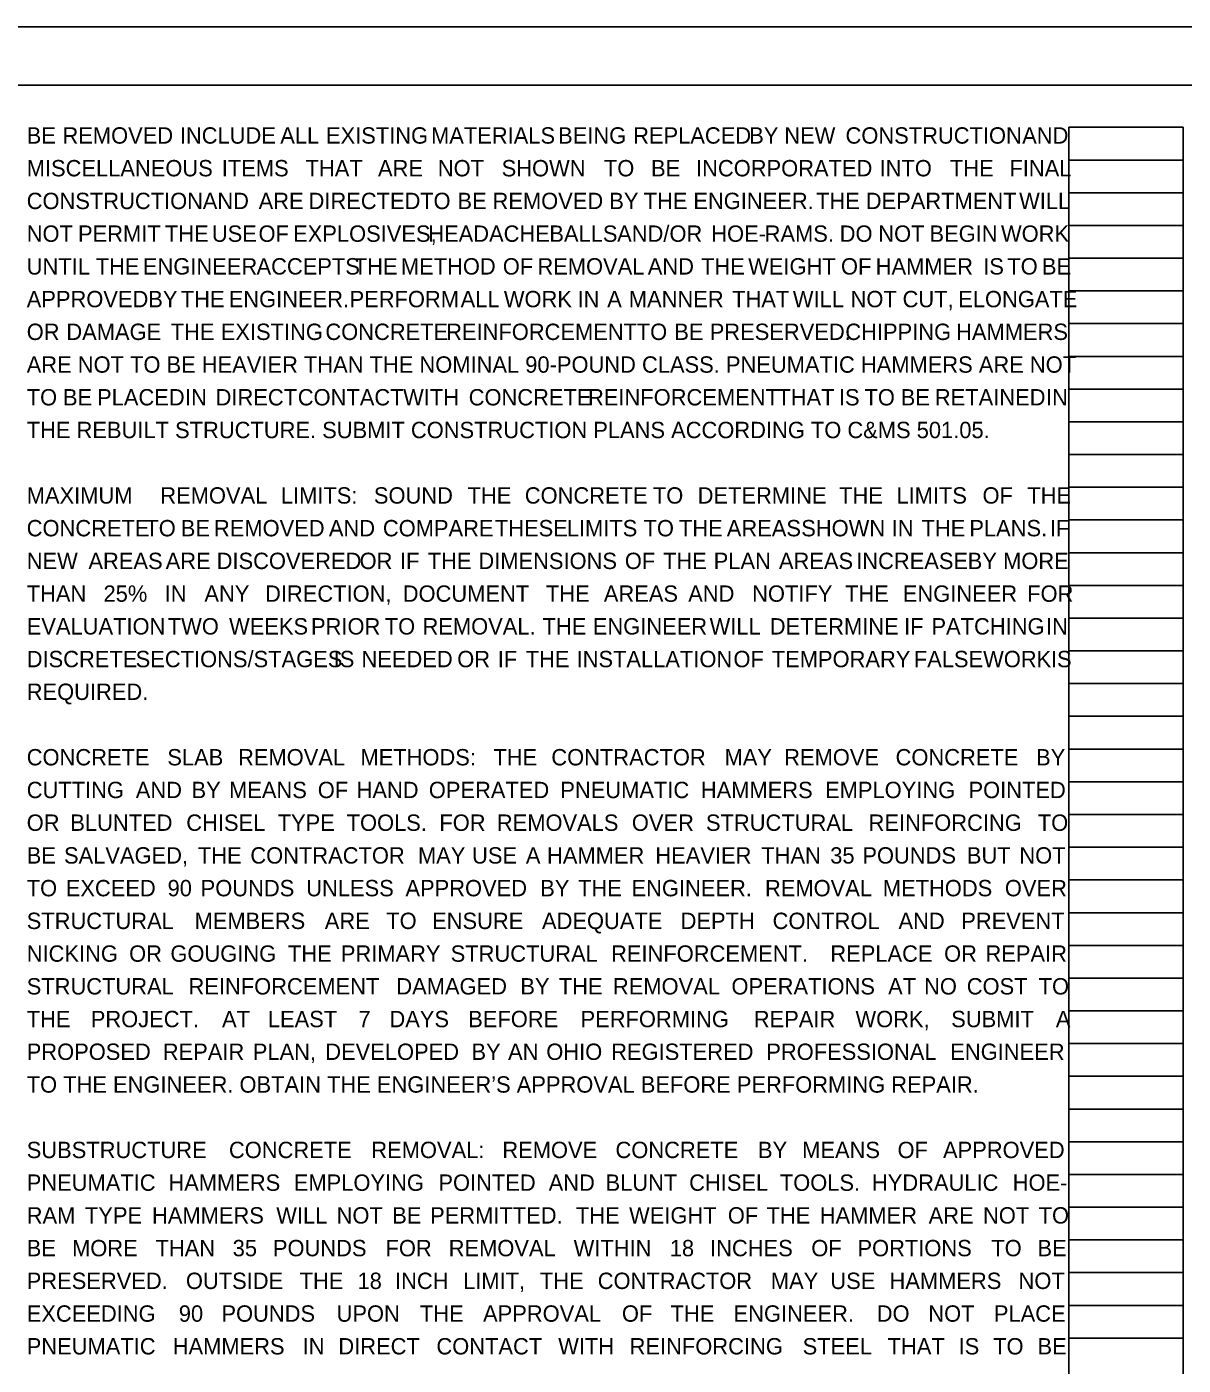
# Model space of a CAD drawing. Extents: x 0 to 44.4, y -4.7 to 22.
# Drawn here: x 12.29 to 22.19, y 10.55 to 22 of the extents above; entities that cross this region are included whole.
import ezdxf

# ---------------------------------------------------------------- set-up
doc = ezdxf.new("R2010")
doc.units = 0
for name, color, linetype in [('SC_Scratch1', 7, 'Continuous'), ('SH_Border', 7, 'Continuous'), ('SH_Cut_Line', 7, 'Continuous'), ('SH_Text', 7, 'Continuous')]:
    doc.layers.add(name, color=color, linetype=linetype)

msp = doc.modelspace()

# ---------------------------------------------------------------- linework, layer by layer
at = {"layer": 'SC_Scratch1'}
for p, q in [((21.207, 0.98), (21.207, 21.14)), ((21.207, 21.14), (22.187, 21.14)), ((22.187, 0.98), (22.187, 21.14)), ((21.207, 20.86), (22.187, 20.86)), ((21.207, 20.58), (22.187, 20.58)), ((21.207, 20.3), (22.187, 20.3)), ((21.207, 20.02), (22.187, 20.02)), ((21.207, 19.74), (22.187, 19.74)), ((21.207, 19.46), (22.187, 19.46)), ((21.207, 19.18), (22.187, 19.18)), ((21.207, 18.9), (22.187, 18.9)), ((21.207, 18.62), (22.187, 18.62)), ((21.207, 18.34), (22.187, 18.34)), ((21.207, 18.06), (22.187, 18.06)), ((21.207, 17.78), (22.187, 17.78)), ((21.207, 17.5), (22.187, 17.5)), ((21.207, 17.22), (22.187, 17.22)), ((21.207, 16.94), (22.187, 16.94)), ((21.207, 16.66), (22.187, 16.66)), ((21.207, 16.38), (22.187, 16.38)), ((21.207, 16.1), (22.187, 16.1)), ((21.207, 15.82), (22.187, 15.82)), ((21.207, 15.54), (22.187, 15.54)), ((21.207, 15.26), (22.187, 15.26)), ((21.207, 14.98), (22.187, 14.98)), ((21.207, 14.7), (22.187, 14.7)), ((21.207, 14.42), (22.187, 14.42)), ((21.207, 14.14), (22.187, 14.14)), ((21.207, 13.86), (22.187, 13.86)), ((21.207, 13.58), (22.187, 13.58)), ((21.207, 13.3), (22.187, 13.3)), ((21.207, 13.02), (22.187, 13.02)), ((21.207, 12.74), (22.187, 12.74)), ((21.207, 12.46), (22.187, 12.46)), ((21.207, 12.18), (22.187, 12.18)), ((21.207, 11.9), (22.187, 11.9)), ((21.207, 11.62), (22.187, 11.62)), ((21.207, 11.34), (22.187, 11.34)), ((21.207, 11.06), (22.187, 11.06)), ((21.207, 10.78), (22.187, 10.78))]:
    msp.add_line(p, q, dxfattribs=at)
msp.add_lwpolyline([(0, 22), (34, 22), (34, 0), (0, 0)], close=True, dxfattribs=at)
at = {"layer": 'SH_Border'}
msp.add_lwpolyline([(1.5, 21.5), (33.5, 21.5), (33.5, 0.5), (1.5, 0.5)], close=True, dxfattribs=at)
at = {"layer": 'SH_Cut_Line'}
msp.add_lwpolyline([(0, 0), (34, 0), (34, 22), (0, 22)], close=True, dxfattribs=at)

# ---------------------------------------------------------------- texts
at = {"layer": 'SH_Text'}
for s, p in [('BE ', (12.293, 21)), ('REMOVED ', (12.599, 21)), ('INCLUDE ', (13.603, 21)), ('ALL ', (14.462, 21)), ('EXISTING ', (14.853, 21)), ('MATERIALS ', (15.752, 21)), ('BEING ', (16.839, 21)), ('REPLACED ', (17.481, 21)), ('BY ', (18.474, 21)), ('NEW ', (18.774, 21)), ('CONSTRUCTION ', (19.298, 21)), ('AND ', (20.809, 21)), ('MISCELLANEOUS ', (12.293, 20.72)), ('ITEMS ', (13.962, 20.72)), ('THAT ', (14.679, 20.72)), ('ARE ', (15.298, 20.72)), ('NOT ', (15.81, 20.72)), ('SHOWN ', (16.356, 20.72)), ('TO ', (17.231, 20.72)), ('BE ', (17.634, 20.72)), ('INCORPORATED ', (18.019, 20.72)), ('INTO ', (19.589, 20.72)), ('THE ', (20.191, 20.72)), ('FINAL ', (20.7, 20.72)), ('CONSTRUCTION ', (12.293, 20.44)), ('AND ', (13.799, 20.44)), ('ARE ', (14.277, 20.44)), ('DIRECTED ', (14.704, 20.44)), ('TO ', (15.659, 20.44)), ('BE ', (15.978, 20.44)), ('REMOVED ', (16.278, 20.44)), ('BY ', (17.277, 20.44)), ('THE ', (17.571, 20.44)), ('ENGINEER. ', (17.996, 20.44)), ('THE ', (19.046, 20.44)), ('DEPARTMENT ', (19.471, 20.44)), ('WILL ', (20.783, 20.44)), ('NOT ', (12.293, 20.16)), ('PERMIT ', (12.732, 20.16)), ('THE ', (13.475, 20.16)), ('USE ', (13.877, 20.16)), ('OF ', (14.276, 20.16)), ('EXPLOSIVES, ', (14.572, 20.16)), ('HEADACHE ', (15.728, 20.16)), ('BALLS ', (16.764, 20.16)), ('AND/OR ', (17.344, 20.16)), ('HOE-', (18.149, 20.16)), ('RAMS. ', (18.606, 20.16)), ('DO ', (19.248, 20.16)), ('NOT ', (19.578, 20.16)), ('BEGIN ', (20.016, 20.16)), ('WORK ', (20.628, 20.16)), ('UNTIL ', (12.293, 19.88)), ('THE ', (12.883, 19.88)), ('ENGINEER ', (13.287, 19.88)), ('ACCEPTS ', (14.259, 19.88)), ('THE ', (15.091, 19.88)), ('METHOD ', (15.494, 19.88)), ('OF ', (16.366, 19.88)), ('REMOVAL ', (16.662, 19.88)), ('AND ', (17.606, 19.88)), ('THE ', (18.062, 19.88)), ('WEIGHT ', (18.465, 19.88)), ('OF ', (19.259, 19.88)), ('HAMMER ', (19.556, 19.88)), ('IS ', (20.476, 19.88)), ('TO ', (20.682, 19.88)), ('BE ', (20.978, 19.88)), ('APPROVED ', (12.293, 19.6)), ('BY ', (13.333, 19.6)), ('THE ', (13.611, 19.6)), ('ENGINEER. ', (14.021, 19.6)), ('PERFORM ', (15.055, 19.6)), ('ALL ', (16.005, 19.6)), ('WORK ', (16.375, 19.6)), ('IN ', (17.005, 19.6)), ('A ', (17.259, 19.6)), ('MANNER ', (17.444, 19.6)), ('THAT ', (18.328, 19.6)), ('WILL ', (18.847, 19.6)), ('NOT ', (19.341, 19.6)), ('CUT, ', (19.786, 19.6)), ('ELONGATE ', (20.262, 19.6)), ('OR ', (12.293, 19.32)), ('DAMAGE ', (12.632, 19.32)), ('THE ', (13.525, 19.32)), ('EXISTING ', (13.953, 19.32)), ('CONCRETE ', (14.848, 19.32)), ('REINFORCEMENT ', (15.881, 19.32)), ('TO ', (17.512, 19.32)), ('BE ', (17.833, 19.32)), ('PRESERVED. ', (18.136, 19.32)), ('CHIPPING ', (19.296, 19.32)), ('HAMMERS ', (20.244, 19.32)), ('ARE NOT TO BE HEAVIER THAN THE NOMINAL 90-POUND CLASS. PNEUMATIC HAMMERS ARE NOT ', (12.293, 19.04)), ('TO ', (12.293, 18.76)), ('BE ', (12.603, 18.76)), ('PLACED ', (12.895, 18.76)), ('IN ', (13.647, 18.76)), ('DIRECT ', (13.909, 18.76)), ('CONTACT ', (14.612, 18.76)), ('WITH ', (15.513, 18.76)), ('CONCRETE ', (16.074, 18.76)), ('REINFORCEMENT ', (17.095, 18.76)), ('THAT ', (18.715, 18.76)), ('IS ', (19.241, 18.76)), ('TO ', (19.46, 18.76)), ('BE ', (19.77, 18.76)), ('RETAINED ', (20.062, 18.76)), ('IN ', (21.013, 18.76)), ('THE REBUILT STRUCTURE. SUBMIT CONSTRUCTION PLANS ACCORDING TO C&MS 501.05. ', (12.293, 18.48)), ('MAXIMUM ', (12.293, 17.92)), ('REMOVAL ', (13.436, 17.92)), ('LIMITS: ', (14.467, 17.92)), ('SOUND ', (15.263, 17.92)), ('THE ', (16.064, 17.92)), ('CONCRETE ', (16.554, 17.92)), ('TO ', (17.65, 17.92)), ('DETERMINE ', (18.033, 17.92)), ('THE ', (19.243, 17.92)), ('LIMITS ', (19.733, 17.92)), ('OF ', (20.47, 17.92)), ('THE ', (20.853, 17.92)), ('CONCRETE ', (12.293, 17.64)), ('TO ', (13.308, 17.64)), ('BE ', (13.611, 17.64)), ('REMOVED ', (13.895, 17.64)), ('AND ', (14.878, 17.64)), ('COMPARE ', (15.34, 17.64)), ('THESE ', (16.298, 17.64)), ('LIMITS ', (16.913, 17.64)), ('TO ', (17.57, 17.64)), ('THE ', (17.873, 17.64)), ('AREAS ', (18.282, 17.64)), ('SHOWN ', (18.919, 17.64)), ('IN ', (19.693, 17.64)), ('THE ', (19.948, 17.64)), ('PLANS. ', (20.357, 17.64)), ('IF ', (21.046, 17.64)), ('NEW ', (12.293, 17.36)), ('AREAS ', (12.821, 17.36)), ('ARE ', (13.482, 17.36)), ('DISCOVERED ', (13.918, 17.36)), ('OR ', (15.141, 17.36)), ('IF ', (15.486, 17.36)), ('THE ', (15.724, 17.36)), ('DIMENSIONS ', (16.157, 17.36)), ('OF ', (17.41, 17.36)), ('THE ', (17.737, 17.36)), ('PLAN ', (18.17, 17.36)), ('AREAS ', (18.728, 17.36)), ('INCREASE ', (19.389, 17.36)), ('BY ', (20.343, 17.36)), ('MORE ', (20.646, 17.36)), ('THAN ', (12.293, 17.08)), ('25% ', (12.95, 17.08)), ('IN ', (13.473, 17.08)), ('ANY ', (13.813, 17.08)), ('DIRECTION, ', (14.332, 17.08)), ('DOCUMENT ', (15.51, 17.08)), ('THE ', (16.735, 17.08)), ('AREAS ', (17.23, 17.08)), ('AND ', (17.952, 17.08)), ('NOTIFY ', (18.499, 17.08)), ('THE ', (19.294, 17.08)), ('ENGINEER ', (19.788, 17.08)), ('FOR ', (20.852, 17.08)), ('EVALUATION ', (12.293, 16.8)), ('TWO ', (13.5, 16.8)), ('WEEKS ', (14.024, 16.8)), ('PRIOR ', (14.725, 16.8)), ('TO ', (15.356, 16.8)), ('REMOVAL. ', (15.679, 16.8)), ('THE ', (16.706, 16.8)), ('ENGINEER ', (17.136, 16.8)), ('WILL ', (18.135, 16.8)), ('DETERMINE ', (18.65, 16.8)), ('IF ', (19.799, 16.8)), ('PATCHING ', (20.033, 16.8)), ('IN ', (21.013, 16.8)), ('DISCRETE ', (12.293, 16.52)), ('SECTIONS/STAGES ', (13.225, 16.52)), ('IS ', (14.919, 16.52)), ('NEEDED ', (15.157, 16.52)), ('OR ', (15.976, 16.52)), ('IF ', (16.323, 16.52)), ('THE ', (16.562, 16.52)), ('INSTALLATION ', (16.997, 16.52)), ('OF ', (18.339, 16.52)), ('TEMPORARY ', (18.667, 16.52)), ('FALSEWORK ', (19.882, 16.52)), ('IS ', (21.055, 16.52)), ('REQUIRED.', (12.293, 16.24)), ('CONCRETE ', (12.293, 15.68)), ('SLAB ', (13.496, 15.68)), ('REMOVAL ', (14.101, 15.68)), ('METHODS: ', (15.148, 15.68)), ('THE ', (16.285, 15.68)), ('CONTRACTOR ', (16.781, 15.68)), ('MAY ', (18.263, 15.68)), ('REMOVE ', (18.773, 15.68)), ('CONCRETE ', (19.726, 15.68)), ('BY ', (20.928, 15.68)), ('CUTTING ', (12.293, 15.4)), ('AND ', (13.226, 15.4)), ('BY ', (13.703, 15.4)), ('MEANS ', (14.024, 15.4)), ('OF ', (14.783, 15.4)), ('HAND ', (15.115, 15.4)), ('OPERATED ', (15.733, 15.4)), ('PNEUMATIC ', (16.858, 15.4)), ('HAMMERS ', (18.06, 15.4)), ('EMPLOYING ', (19.123, 15.4)), ('POINTED ', (20.35, 15.4)), ('OR ', (12.293, 15.12)), ('BLUNTED ', (12.666, 15.12)), ('CHISEL ', (13.658, 15.12)), ('TYPE ', (14.44, 15.12)), ('TOOLS. ', (15.03, 15.12)), ('FOR ', (15.823, 15.12)), ('REMOVALS ', (16.315, 15.12)), ('OVER ', (17.47, 15.12)), ('STRUCTURAL ', (18.104, 15.12)), ('REINFORCING ', (19.495, 15.12)), ('TO ', (20.943, 15.12)), ('BE ', (12.293, 14.84)), ('SALVAGED, ', (12.612, 14.84)), ('THE ', (13.757, 14.84)), ('CONTRACTOR ', (14.206, 14.84)), ('MAY ', (15.64, 14.84)), ('USE ', (16.103, 14.84)), ('A ', (16.563, 14.84)), ('HAMMER ', (16.744, 14.84)), ('HEAVIER ', (17.671, 14.84)), ('THAN ', (18.577, 14.84)), ('35 ', (19.167, 14.84)), ('POUNDS ', (19.442, 14.84)), ('BUT ', (20.336, 14.84)), ('NOT ', (20.785, 14.84)), ('TO ', (12.293, 14.56)), ('EXCEED ', (12.627, 14.56)), ('90 ', (13.498, 14.56)), ('POUNDS ', (13.781, 14.56)), ('UNLESS ', (14.684, 14.56)), ('APPROVED ', (15.533, 14.56)), ('BY ', (16.686, 14.56)), ('THE ', (17.01, 14.56)), ('ENGINEER. ', (17.467, 14.56)), ('REMOVAL ', (18.609, 14.56)), ('METHODS ', (19.617, 14.56)), ('OVER ', (20.661, 14.56)), ('STRUCTURAL ', (12.293, 14.28)), ('MEMBERS ', (13.729, 14.28)), ('ARE ', (14.843, 14.28)), ('TO ', (15.369, 14.28)), ('ENSURE ', (15.761, 14.28)), ('ADEQUATE ', (16.701, 14.28)), ('DEPTH ', (17.887, 14.28)), ('CONTROL ', (18.674, 14.28)), ('AND ', (19.751, 14.28)), ('PREVENT ', (20.288, 14.28)), ('NICKING ', (12.293, 14)), ('OR ', (13.169, 14)), ('GOUGING ', (13.522, 14)), ('THE ', (14.528, 14)), ('PRIMARY ', (14.98, 14)), ('STRUCTURAL ', (15.92, 14)), ('REINFORCEMENT.  ', (17.292, 14)), ('REPLACE ', (19.168, 14)), ('OR ', (20.141, 14)), ('REPAIR ', (20.495, 14)), ('STRUCTURAL ', (12.293, 13.72)), ('REINFORCEMENT ', (13.677, 13.72)), ('DAMAGED ', (15.455, 13.72)), ('BY ', (16.516, 13.72)), ('THE ', (16.845, 13.72)), ('REMOVAL ', (17.308, 13.72)), ('OPERATIONS ', (18.322, 13.72)), ('AT ', (19.662, 13.72)), ('NO ', (19.97, 13.72)), ('COST ', (20.335, 13.72)), ('TO ', (20.95, 13.72)), ('THE ', (12.293, 13.44)), ('PROJECT. ', (12.841, 13.44)), ('AT ', (13.964, 13.44)), ('LEAST ', (14.356, 13.44)), ('7 ', (15.131, 13.44)), ('DAYS ', (15.396, 13.44)), ('BEFORE ', (16.07, 13.44)), ('PERFORMING ', (17.031, 13.44)), ('REPAIR ', (18.513, 13.44)), ('WORK, ', (19.383, 13.44)), ('SUBMIT ', (20.202, 13.44)), ('A ', (21.097, 13.44)), ('PROPOSED ', (12.293, 13.16)), ('REPAIR ', (13.457, 13.16)), ('PLAN, ', (14.227, 13.16)), ('DEVELOPED ', (14.847, 13.16)), ('BY ', (16.098, 13.16)), ('AN ', (16.411, 13.16)), ('OHIO ', (16.738, 13.16)), ('REGISTERED ', (17.293, 13.16)), ('PROFESSIONAL ', (18.62, 13.16)), ('ENGINEER ', (20.194, 13.16)), ('TO THE ENGINEER. OBTAIN THE ENGINEER’S APPROVAL BEFORE PERFORMING REPAIR.', (12.293, 12.88)), ('SUBSTRUCTURE ', (12.293, 12.32)), ('CONCRETE ', (14.023, 12.32)), ('REMOVAL: ', (15.241, 12.32)), ('REMOVE ', (16.362, 12.32)), ('CONCRETE ', (17.33, 12.32)), ('BY ', (18.549, 12.32)), ('MEANS ', (18.927, 12.32)), ('OF ', (19.743, 12.32)), ('APPROVED ', (20.132, 12.32)), ('PNEUMATIC ', (12.293, 12.04)), ('HAMMERS ', (13.505, 12.04)), ('EMPLOYING ', (14.578, 12.04)), ('POINTED ', (15.815, 12.04)), ('AND ', (16.758, 12.04)), ('BLUNT ', (17.245, 12.04)), ('CHISEL ', (17.96, 12.04)), ('TOOLS. ', (18.736, 12.04)), ('HYDRAULIC ', (19.524, 12.04)), ('HOE-', (20.728, 12.04)), ('RAM ', (12.293, 11.76)), ('TYPE ', (12.791, 11.76)), ('HAMMERS ', (13.365, 11.76)), ('WILL ', (14.428, 11.76)), ('NOT ', (14.944, 11.76)), ('BE ', (15.42, 11.76)), ('PERMITTED. ', (15.744, 11.76)), ('THE ', (16.991, 11.76)), ('WEIGHT ', (17.446, 11.76)), ('OF ', (18.291, 11.76)), ('THE ', (18.622, 11.76)), ('HAMMER ', (19.077, 11.76)), ('ARE ', (20.009, 11.76)), ('NOT ', (20.474, 11.76)), ('TO ', (20.95, 11.76)), ('BE ', (12.293, 11.48)), ('MORE ', (12.681, 11.48)), ('THAN ', (13.395, 11.48)), ('35 ', (14.055, 11.48)), ('POUNDS ', (14.399, 11.48)), ('FOR ', (15.363, 11.48)), ('REMOVAL ', (15.903, 11.48)), ('WITHIN ', (16.972, 11.48)), ('18 ', (17.794, 11.48)), ('INCHES ', (18.139, 11.48)), ('OF ', (19.005, 11.48)), ('PORTIONS ', (19.4, 11.48)), ('TO ', (20.545, 11.48)), ('BE ', (20.94, 11.48)), ('PRESERVED. ', (12.293, 11.2)), ('OUTSIDE ', (13.655, 11.2)), ('THE ', (14.628, 11.2)), ('18 ', (15.123, 11.2)), ('INCH ', (15.444, 11.2)), ('LIMIT, ', (16.026, 11.2)), ('THE ', (16.683, 11.2)), ('CONTRACTOR ', (17.178, 11.2)), ('MAY ', (18.659, 11.2)), ('USE ', (19.168, 11.2)), ('HAMMERS ', (19.674, 11.2)), ('NOT ', (20.778, 11.2)), ('EXCEEDING ', (12.293, 10.92)), ('90 ', (13.594, 10.92)), ('POUNDS ', (13.959, 10.92)), ('UPON ', (14.944, 10.92)), ('THE ', (15.657, 10.92)), ('APPROVAL ', (16.197, 10.92)), ('OF ', (17.385, 10.92)), ('THE ', (17.801, 10.92)), ('ENGINEER. ', (18.34, 10.92)), ('DO ', (19.565, 10.92)), ('NOT ', (20.006, 10.92)), ('PLACE ', (20.567, 10.92)), ('PNEUMATIC ', (12.293, 10.64)), ('HAMMERS ', (13.542, 10.64)), ('IN ', (14.653, 10.64)), ('DIRECT ', (14.959, 10.64)), ('CONTACT ', (15.798, 10.64)), ('WITH ', (16.84, 10.64)), ('REINFORCING ', (17.451, 10.64)), ('STEEL ', (18.931, 10.64)), ('THAT ', (19.658, 10.64)), ('IS ', (20.265, 10.64)), ('TO ', (20.561, 10.64)), ('BE ', (20.94, 10.64))]:
    msp.add_text(s, height=0.14, dxfattribs=at).set_placement(p)

doc.saveas('drawing.dxf')
